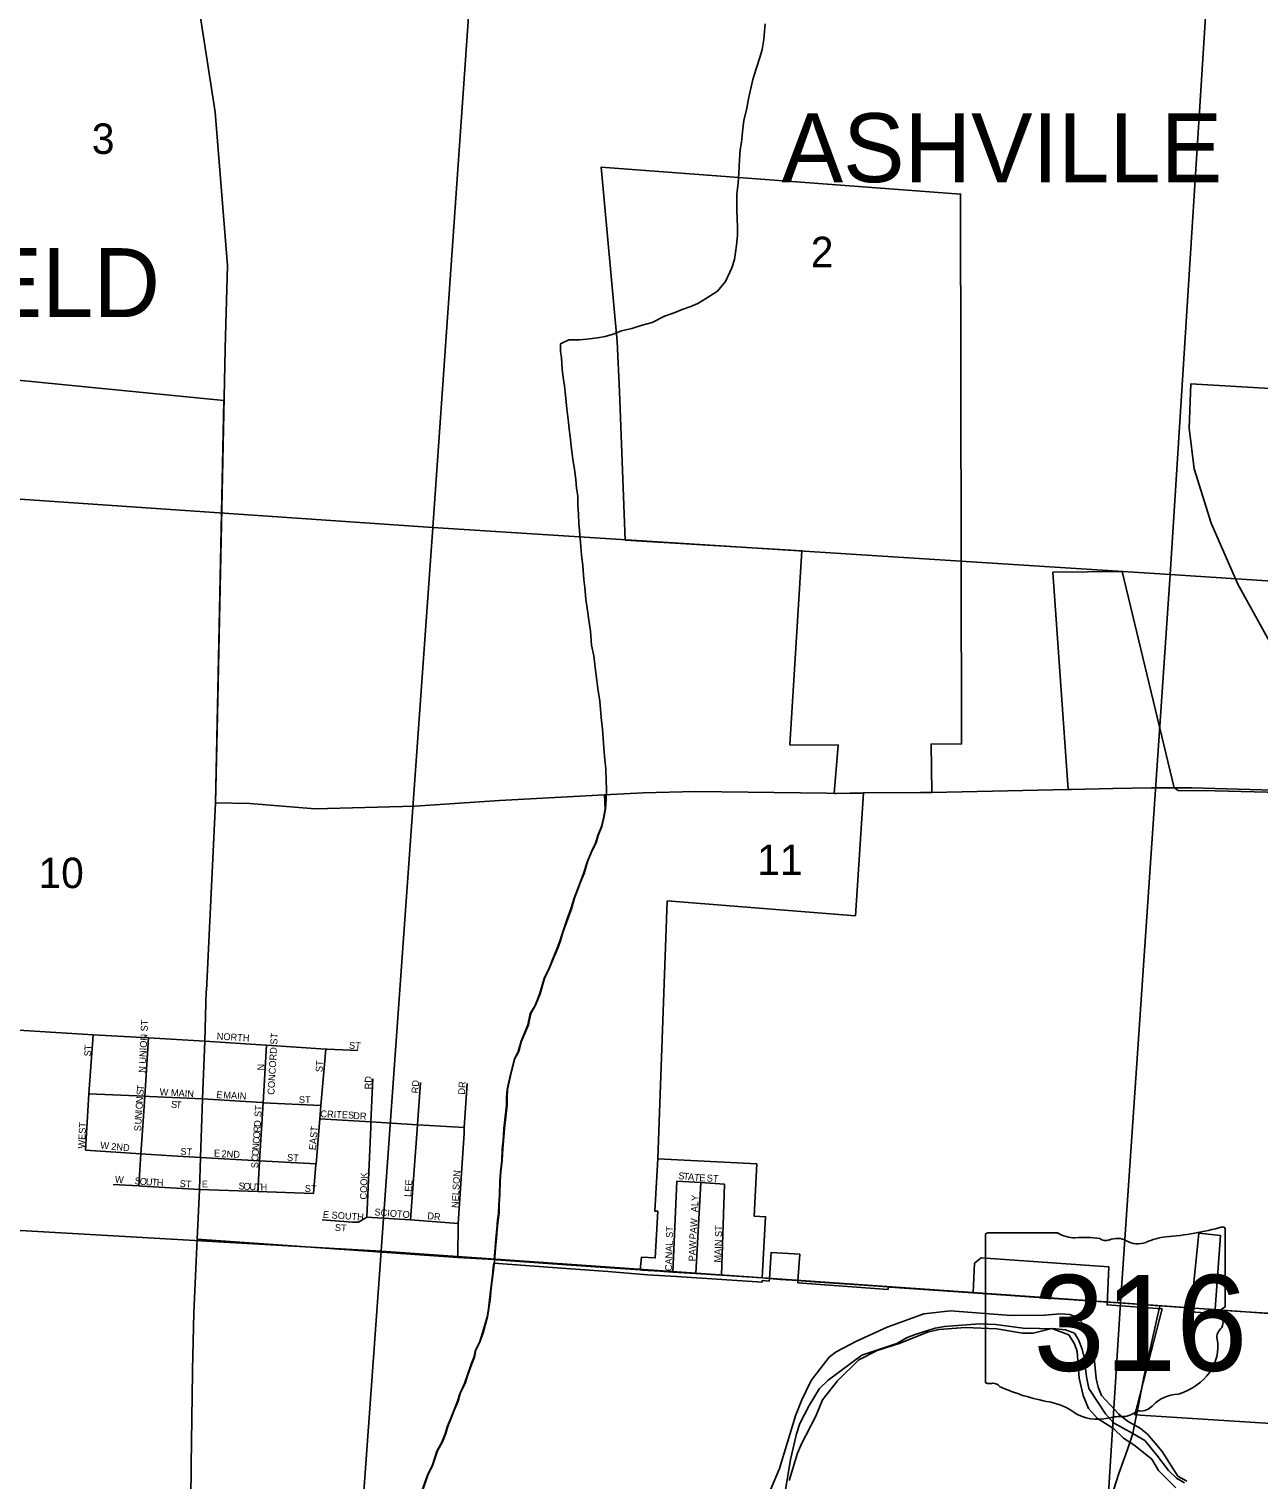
# Model space of a CAD drawing. Extents: x 1643459 to 2064572, y 425441 to 780708.
# Drawn here: x 1830277 to 1839200, y 623125 to 633650 of the extents above; entities that cross this region are included whole.
import ezdxf

# ---------------------------------------------------------------- set-up
doc = ezdxf.new("R2010")
doc.units = 0
for name, color, linetype in [('GM_P_County_Alignment', 7, 'Continuous'), ('GM_X_Adjacent_County', 7, 'Continuous'), ('GM_X_Airport_Class_2', 7, 'Continuous'), ('GM_X_Airport_Class_3', 7, 'Continuous'), ('GM_X_City_Street', 7, 'Continuous'), ('GM_X_Minor_Lake', 7, 'Continuous'), ('GM_X_Rail_Line_Text', 7, 'Continuous'), ('GM_X_State_Route', 7, 'Continuous'), ('GM_X_Unincorporated_Text', 7, 'Continuous'), ('GM_X_US_Route', 7, 'Continuous'), ('PM_P_Cells', 7, 'Continuous'), ('RD_X_Text', 7, 'Continuous'), ('RD_X_Wall', 7, 'Continuous'), ('ST_Details', 7, 'Continuous')]:
    doc.layers.add(name, color=color, linetype=linetype)

msp = doc.modelspace()

# ---------------------------------------------------------------- linework, layer by layer
at = {"layer": 'GM_X_Airport_Class_2'}
for points in [[(1830688, 625512), (1830711, 625921), (1830743, 626350)], [(1831117, 625903), (1831143, 626327)], [(1831552, 626304), (1831996, 626274)], [(1831987, 626065), (1831987, 626065), (1831999, 626274)], [(1831996, 626274), (1831999, 626274), (1832430, 626246), (1832440, 626246)], [(1832359, 625407), (1832359, 625407), (1832360, 625413), (1832387, 625739), (1832395, 625835), (1832430, 626246)], [(1832440, 626246), (1832662, 626235)], [(1831975, 625856), (1831987, 626065)], [(1832756, 625679), (1832756, 625679), (1832758, 625717), (1832772, 626030)], [(1830711, 625921), (1831117, 625903), (1831151, 625902)], [(1833045, 625005), (1833095, 625696), (1833117, 626003)], [(1833433, 625642), (1833435, 625676), (1833456, 625995)], [(1831102, 625686), (1831102, 625686), (1831117, 625903)], [(1831151, 625902), (1831372, 625892), (1831372, 625892)], [(1831372, 625892), (1831537, 625885)], [(1831537, 625885), (1831966, 625857)], [(1831949, 625426), (1831949, 625426), (1831950, 625435), (1831975, 625856)], [(1831966, 625857), (1831975, 625856), (1832395, 625835)], [(1832387, 625739), (1832758, 625717), (1833095, 625696), (1833435, 625676)], [(1831074, 625252), (1831089, 625486), (1831102, 625686)], [(1832727, 625025), (1832756, 625679)], [(1833388, 624733), (1833391, 624979), (1833433, 625635), (1833433, 625642)], [(1830688, 625512), (1831089, 625486), (1831313, 625471)], [(1831313, 625471), (1831313, 625471), (1831521, 625458)], [(1831521, 625458), (1831950, 625435), (1832360, 625413)], [(1831937, 625211), (1831949, 625426)], [(1832342, 625197), (1832359, 625407)], [(1834947, 624627), (1834976, 625287)], [(1834976, 625287), (1835150, 625276), (1835323, 625266)], [(1835114, 624617), (1835150, 625276)], [(1830888, 625263), (1831074, 625252), (1831096, 625251)], [(1831096, 625251), (1831096, 625251), (1831513, 625227)], [(1831513, 625227), (1831937, 625211), (1832342, 625197)], [(1835300, 624604), (1835323, 625266)], [(1832404, 625006), (1832624, 624989), (1832668, 624989), (1832727, 625025)], [(1832727, 625025), (1833045, 625005), (1833391, 624979)]]:
    msp.add_lwpolyline(points, dxfattribs=at)
at = {"layer": 'GM_X_City_Street'}
for points in [[(1838659, 623097), (1838603, 623132), (1838543, 623187), (1838460, 623299), (1838372, 623404), (1838285, 623456), (1838146, 623533), (1838086, 623599), (1838031, 623683), (1837966, 623781), (1837948, 623867), (1837932, 624007), (1837917, 624068), (1837891, 624134), (1837861, 624184), (1837797, 624207), (1837727, 624215), (1837490, 624220), (1837291, 624247), (1837175, 624251), (1836918, 624231), (1836852, 624219), (1836705, 624173), (1836643, 624149), (1836572, 624108), (1836319, 624024), (1836074, 623843), (1836013, 623781), (1835936, 623659), (1835870, 623527), (1835845, 623452), (1835802, 623266), (1835749, 622945)], [(1835749, 622945), (1835802, 623266), (1835845, 623452), (1835870, 623527), (1835936, 623659), (1836013, 623781), (1836074, 623843), (1836319, 624024), (1836572, 624108), (1836643, 624149), (1836705, 624173), (1836852, 624219), (1836918, 624231), (1837175, 624251), (1837291, 624247), (1837490, 624220), (1837727, 624215), (1837797, 624207), (1837861, 624184), (1837891, 624134), (1837917, 624068), (1837932, 624007), (1837948, 623867), (1837966, 623781), (1838031, 623683), (1838086, 623599), (1838146, 623533), (1838285, 623456), (1838372, 623404), (1838460, 623299), (1838543, 623187), (1838603, 623132), (1838659, 623097)]]:
    msp.add_lwpolyline(points, dxfattribs=at)
at = {"layer": 'GM_X_Minor_Lake'}
for points in [[(1838481, 624383), (1838365, 623864), (1838326, 623662)], [(1838326, 623662), (1838295, 623507)], [(1838295, 623507), (1838285, 623456), (1838247, 623339), (1838184, 623166), (1838148, 623052), (1838100, 622903), (1838084, 622769), (1837635, 615362), (1837553, 614083), (1837539, 613880), (1837533, 613820), (1837500, 613782), (1837469, 613757), (1837434, 613737), (1835908, 613841)]]:
    msp.add_lwpolyline(points, dxfattribs=at)
at = {"layer": 'GM_X_Rail_Line_Text'}
for points in [[(1840388, 623458), (1838300, 623591), (1838497, 624360), (1838099, 624388), (1838112, 624664), (1837186, 624730), (1837136, 624691), (1837126, 624478), (1836510, 624519), (1836509, 624501), (1835855, 624548), (1835856, 624565), (1835869, 624756), (1835661, 624769), (1835649, 624580), (1835597, 624584), (1835621, 625028), (1835537, 625033), (1835557, 625412), (1834838, 625450), (1834908, 627321), (1836273, 627213), (1836332, 628105), (1836133, 628101), (1836118, 628101), (1836148, 628452), (1835798, 628453), (1835885, 629861), (1834603, 629940), (1834561, 631019), (1834545, 631381), (1834429, 632648), (1837036, 632451), (1837043, 628461), (1836822, 628459), (1836826, 628109), (1837816, 628130), (1837706, 629707), (1838209, 629711), (1838586, 628143), (1838614, 628123), (1838883, 628120), (1840487, 628080)], [(1823289, 631784), (1831691, 630954), (1831631, 628034), (1831879, 628029), (1832353, 627990), (1833077, 628008), (1833690, 628049), (1834452, 628091), (1834457, 627986), (1834444, 627922), (1834430, 627860), (1834404, 627795), (1834387, 627741), (1834357, 627679), (1834327, 627603), (1834300, 627519), (1834276, 627455), (1834256, 627405), (1834231, 627341), (1834209, 627263), (1834182, 627190), (1834148, 627090), (1834129, 627030), (1834109, 626978), (1834087, 626926), (1834050, 626834), (1834014, 626758), (1833981, 626645), (1833949, 626563), (1833914, 626503), (1833896, 626421), (1833847, 626303), (1833827, 626227), (1833799, 626175), (1833772, 626070), (1833758, 626008), (1833745, 625952), (1833741, 625894), (1833741, 625838), (1833730, 625731), (1833722, 625669), (1833716, 625579), (1833711, 625523), (1833707, 625436), (1833697, 625354), (1833692, 625288), (1833690, 625186), (1833686, 625117), (1833683, 625055), (1833677, 625003), (1833671, 624939), (1833664, 624869), (1833658, 624803), (1833652, 624718), (1834076, 624688), (1834712, 624643), (1834720, 624735), (1834820, 624730), (1834838, 625069), (1834818, 625070), (1834838, 625450), (1835557, 625412), (1835537, 625033), (1835621, 625028), (1835597, 624584), (1835649, 624580), (1835648, 624562), (1835596, 624565), (1835595, 624553), (1834974, 624594), (1834764, 624608), (1834477, 624630), (1834075, 624659), (1833649, 624691), (1833645, 624660), (1833639, 624602), (1833627, 624508), (1833618, 624425), (1833610, 624361), (1833600, 624301), (1833567, 624185), (1833545, 624117), (1833516, 624061), (1833504, 624008), (1833486, 623958), (1833455, 623874), (1833437, 623818), (1833402, 623744), (1833386, 623690), (1833356, 623616), (1833337, 623566), (1833311, 623504), (1833297, 623453), (1833273, 623393), (1833236, 623327), (1833204, 623227), (1833167, 623153), (1833128, 623039)], [(1839797, 628264), (1839046, 629620), (1838853, 630064), (1838731, 630457), (1838695, 630753), (1838707, 631075), (1841089, 630934)]]:
    msp.add_lwpolyline(points, dxfattribs=at)
msp.add_lwpolyline([(1838707, 624338), (1838880, 624327), (1838921, 624893), (1838765, 624909)], close=True, dxfattribs=at)
at = {"layer": 'GM_X_State_Route'}
for points in [[(1828361, 635812), (1833582, 635406), (1833207, 630031), (1828130, 630380)], [(1833582, 635406), (1838893, 635002), (1838557, 629690), (1833207, 630031)], [(1838893, 635002), (1844261, 634633), (1843965, 630056), (1843918, 629340), (1838557, 629690)], [(1828130, 630380), (1833207, 630031), (1832831, 624779), (1827931, 625060)], [(1833207, 630031), (1838557, 629690), (1838196, 624403), (1832831, 624779)], [(1838557, 629690), (1843918, 629340), (1843583, 624695), (1843542, 624018), (1838196, 624403)], [(1832831, 624779), (1832446, 619409), (1827729, 619681), (1827931, 625060)], [(1838196, 624403), (1837858, 619041), (1832446, 619409), (1832831, 624779)], [(1843542, 624018), (1843247, 619225), (1843213, 618737), (1837858, 619041), (1838196, 624403)]]:
    msp.add_lwpolyline(points, close=True, dxfattribs=at)
at = {"layer": 'GM_X_Unincorporated_Text'}
for points in [[(1835656, 623047), (1835723, 623201), (1835839, 623584), (1835884, 623700), (1835951, 623839), (1836082, 624009), (1836134, 624049), (1836281, 624126), (1836504, 624228), (1836768, 624323), (1836962, 624346), (1837402, 624312), (1837644, 624315), (1837761, 624324), (1837829, 624318), (1837881, 624300), (1837943, 624233), (1837981, 624173), (1837995, 624103), (1838020, 623854), (1838033, 623791), (1838059, 623731), (1838183, 623596), (1838247, 623544), (1838339, 623493), (1838395, 623447), (1838497, 623324), (1838612, 623145), (1838676, 623110)], [(1835793, 623113), (1835852, 623313), (1835881, 623381), (1835986, 623580), (1836034, 623700), (1836143, 623838), (1836297, 623990), (1836431, 624057), (1836598, 624111), (1836795, 624192), (1836881, 624210), (1837068, 624225), (1837299, 624214), (1837485, 624183), (1837562, 624183), (1837698, 624218), (1837820, 624172), (1837862, 624107), (1837882, 624051), (1837895, 623858), (1837925, 623730), (1837964, 623637), (1838028, 623565), (1838144, 623492), (1838218, 623421), (1838292, 623373), (1838422, 623268), (1838472, 623187), (1838598, 623060)]]:
    msp.add_lwpolyline(points, dxfattribs=at)
at = {"layer": 'GM_X_US_Route'}
for points in [[(1834296, 629752), (1834286, 629834), (1834280, 629890), (1834275, 629953), (1834267, 630063), (1834263, 630127), (1834260, 630195), (1834258, 630260), (1834250, 630316), (1834244, 630380), (1834235, 630452), (1834223, 630527), (1834213, 630603), (1834202, 630691), (1834196, 630746), (1834190, 630796), (1834180, 630892), (1834169, 630991), (1834163, 631059), (1834153, 631121), (1834146, 631181), (1834140, 631262), (1834132, 631312), (1834132, 631364), (1834193, 631394), (1834271, 631393), (1834325, 631399), (1834401, 631407), (1834456, 631417), (1834516, 631435), (1834576, 631458), (1834651, 631476), (1834725, 631500), (1834797, 631520), (1834888, 631565), (1834958, 631589), (1835016, 631613), (1835079, 631635), (1835129, 631657), (1835193, 631695), (1835272, 631746), (1835330, 631818), (1835377, 631916), (1835395, 631977), (1835403, 632027), (1835410, 632081), (1835416, 632151), (1835416, 632211), (1835413, 632332), (1835413, 632454), (1835422, 632530), (1835426, 632603), (1835431, 632699), (1835437, 632773), (1835445, 632829), (1835456, 632926), (1835464, 632986), (1835484, 633076), (1835495, 633130), (1835511, 633208), (1835529, 633284), (1835552, 633361), (1835578, 633443), (1835595, 633501), (1835609, 633573), (1835613, 633635), (1835618, 633687)], [(1833132, 623040), (1833171, 623154), (1833207, 623228), (1833240, 623329), (1833276, 623395), (1833301, 623455), (1833315, 623505), (1833341, 623567), (1833359, 623617), (1833390, 623691), (1833406, 623745), (1833441, 623819), (1833459, 623875), (1833489, 623960), (1833508, 624010), (1833520, 624062), (1833548, 624118), (1833571, 624186), (1833603, 624302), (1833614, 624362), (1833622, 624427), (1833630, 624509), (1833643, 624603), (1833649, 624661), (1833657, 624732), (1833662, 624804), (1833668, 624870), (1833674, 624940), (1833681, 625004), (1833687, 625057), (1833689, 625119), (1833693, 625187), (1833696, 625289), (1833700, 625355), (1833711, 625438), (1833715, 625524), (1833719, 625580), (1833726, 625670), (1833734, 625733), (1833745, 625839), (1833745, 625895), (1833749, 625953), (1833761, 626009), (1833776, 626072), (1833802, 626176), (1833831, 626228), (1833851, 626304), (1833900, 626422), (1833918, 626504), (1833952, 626565), (1833985, 626647), (1834018, 626759), (1834054, 626835), (1834091, 626927), (1834113, 626979), (1834133, 627031), (1834151, 627091), (1834186, 627192), (1834212, 627264), (1834235, 627342), (1834259, 627406), (1834279, 627456), (1834304, 627520), (1834330, 627604), (1834361, 627681), (1834391, 627743), (1834407, 627797), (1834434, 627861), (1834448, 627923), (1834460, 627987), (1834465, 628055), (1834467, 628132), (1834465, 628192), (1834462, 628280), (1834454, 628346), (1834450, 628401), (1834444, 628467), (1834437, 628567), (1834427, 628652), (1834418, 628770), (1834404, 628862), (1834396, 628921), (1834387, 628997), (1834375, 629099), (1834359, 629178), (1834350, 629280), (1834338, 629360), (1834328, 629429), (1834317, 629511), (1834309, 629597), (1834303, 629653), (1834296, 629752)]]:
    msp.add_lwpolyline(points, dxfattribs=at)
at = {"layer": 'RD_X_Text'}
for points in [[(1836744, 628108), (1836826, 628109), (1837816, 628130), (1837840, 628130)], [(1837840, 628130), (1838139, 628136), (1838421, 628142), (1838459, 628143), (1838466, 628143)], [(1838466, 628143), (1838623, 628143)], [(1838623, 628143), (1838713, 628143), (1839816, 628110), (1839876, 628107)], [(1831631, 628034), (1831879, 628029), (1832353, 627990), (1833077, 628008), (1833690, 628049), (1834452, 628091), (1834499, 628093)], [(1834499, 628093), (1834732, 628105), (1835112, 628115), (1836065, 628102)], [(1836065, 628102), (1836118, 628101), (1836133, 628101), (1836326, 628104)], [(1836326, 628104), (1836332, 628105), (1836744, 628108)], [(1830186, 626383), (1830240, 626380), (1830743, 626350), (1831143, 626327), (1831552, 626304)], [(1831497, 624865), (1833388, 624733), (1833652, 624718), (1833666, 624717)], [(1833666, 624717), (1834384, 624666), (1834712, 624643), (1834724, 624642)], [(1834724, 624642), (1834767, 624639), (1834856, 624633), (1834883, 624631)], [(1834883, 624631), (1834947, 624627), (1835114, 624617), (1835300, 624604), (1835597, 624584), (1835649, 624580), (1835677, 624578)], [(1835677, 624578), (1835730, 624574)], [(1835730, 624574), (1835856, 624565), (1835941, 624559)], [(1835941, 624559), (1836510, 624519), (1836523, 624518)], [(1836523, 624518), (1837158, 624473)], [(1837158, 624473), (1837533, 624447), (1838216, 624401)], [(1838216, 624401), (1838481, 624383)], [(1838481, 624383), (1838840, 624357)], [(1838840, 624357), (1838994, 624346)], [(1838994, 624346), (1839063, 624341), (1839302, 624326)]]:
    msp.add_lwpolyline(points, dxfattribs=at)
at = {"layer": 'RD_X_Wall'}
for points in [[(1831701, 631333), (1831718, 631932), (1831628, 633047), (1830807, 638339), (1830530, 640486), (1831027, 646299)], [(1831642, 628558), (1831701, 631324), (1831701, 631333)], [(1831631, 628034), (1831642, 628558)], [(1831564, 626671), (1831631, 628034)], [(1831552, 626304), (1831563, 626668), (1831564, 626671)], [(1831513, 625225), (1831513, 625227), (1831521, 625458), (1831537, 625885), (1831552, 626304)], [(1831488, 624654), (1831497, 624865), (1831513, 625225)], [(1831464, 623914), (1831474, 624331), (1831488, 624654)], [(1831454, 623227), (1831463, 623898), (1831464, 623914)], [(1831437, 621883), (1831441, 622392), (1831450, 622963), (1831454, 623227)]]:
    msp.add_lwpolyline(points, dxfattribs=at)
at = {"layer": 'ST_Details'}
for p, q in [((1837216, 624892), (1837216, 623836)), ((1837743, 624911), (1837233, 624911)), ((1838956, 624384), (1838956, 624937)), ((1838956, 624384), (1838956, 624384))]:
    msp.add_line(p, q, dxfattribs=at)
for centre, major_axis, start_param, end_param in [((1837236, 624895), (20.2, 0), 1.712693, 3.28349), ((1837864, 625033), (196, 0), 4.042523, 4.731795), ((1837929, 624317), (702, 0), 1.404758, 1.657858), ((1838088, 624900), (56.4, 0), 3.836095, 5.185415), ((1838171, 624778), (117, 0), 0.950623, 2.079405), ((1838322, 624945), (141, 0), 4.081561, 5.145723), ((1838572, 624588), (371, 0), 1.699011, 2.107814), ((1838336, 626351), (1845, 0), 4.814394, 5.042369), ((1838937, 624939), (19.4, 0), 6.141152, 7.989035), ((1838952, 624343), (30, 0), 1.883978, 3.671073), ((1838761, 624274), (180, 0), 5.934695, 6.695948), ((1838935, 624382), (20.7, 0), 5.05454, 6.418171), ((1839026, 624153), (131, 0), 2.387724, 3.262537), ((1838440, 624082), (462, 0), 5.101752, 6.440018), ((1837236, 623833), (20.3, 0), 3.00124, 4.508301), ((1837239, 623942), (155, 0), 4.665946, 4.897461), ((1837271, 623775), (56, 0), 0.519207, 1.627899), ((1837977, 624724), (1333, 0), 4.195997, 4.488961), ((1838634, 623539), (253, 0), 1.647645, 2.488434), ((1837580, 623361), (417, 0), 0.823519, 1.323587), ((1838031, 623770), (265, 0), 4.026481, 4.996735), ((1838203, 623690), (141, 0), 4.691044, 5.507374), ((1838331, 623588), (39.7, 0), 1.147584, 2.315152), ((1838314, 623733), (149, 0), 4.937069, 5.64225), ((1838184, 623404), (217, 0), 1.495662, 1.94098)]:
    msp.add_ellipse(centre, major_axis=major_axis, ratio=0.8, start_param=start_param, end_param=end_param, dxfattribs=at)

# ---------------------------------------------------------------- texts
at = {"layer": 'GM_P_County_Alignment'}
for s, p in [('ASHVILLE', (1835737, 632538)), ('SOUTH BLOOMFIELD', (1824392, 631559))]:
    msp.add_text(s, height=500, rotation=0, dxfattribs=at).set_placement(p)
at = {"layer": 'GM_X_Adjacent_County'}
for s, p in [('3', (1830733, 632743)), ('2', (1835949, 631921)), ('11', (1835560, 627509)), ('10', (1830346, 627414))]:
    msp.add_text(s, height=221, rotation=0, dxfattribs=at).set_placement(p)
at = {"layer": 'GM_X_Airport_Class_3'}
for s, rotation, p in [('N UNION ST', 87.0659, (1831122, 626072)), ('NORTH', 356.4211, (1831638, 626315)), ('CONCORD ST', 86.7505, (1832057, 625913)), ('ST', 86.4254, (1830726, 626191)), ('ST', 356.1734, (1832597, 626249)), ('N', 90, (1831984, 626090)), ('ST', 86.4262, (1832406, 626077)), ('RD', 90, (1832763, 625953)), ('RD', 86.8222, (1833102, 625923)), ('S', 85.8171, (1831107, 625908)), ('T', 85.7878, (1831110, 625943)), ('W MAIN', 356.8193, (1831224, 625910)), ('E', 352.8783, (1831634, 625892)), ('MAIN', 356.9016, (1831686, 625888)), ('DR', 86.8222, (1833440, 625914)), ('O', 85.7773, (1831100, 625807)), ('N', 85.804, (1831103, 625851)), ('S', 355.9533, (1831306, 625820)), ('T', 356.9242, (1831342, 625817)), ('ST', 86.4118, (1831962, 625751)), ('ST', 0, (1832235, 625853)), ('CRITES', 357.6154, (1832390, 625751)), ('WEST', 86.9833, (1830682, 625522)), ('U', 86.2164, (1831092, 625697)), ('N', 85.7991, (1831095, 625741)), ('I', 85.7991, (1831098, 625785)), ('D', 85.7365, (1831958, 625679)), ('DR', 356.989, (1832628, 625738)), ('S', 89.153, (1831091, 625649)), ('C', 85.7476, (1831949, 625556)), ('O', 85.7337, (1831952, 625595)), ('R', 85.7223, (1831955, 625639)), ('EAST', 85.0974, (1832358, 625510)), ('W', 355.6039, (1830793, 625523)), ('2ND', 355.7579, (1830872, 625514)), ('ST', 356.4254, (1831374, 625479)), ('E', 0, (1831619, 625465)), ('2ND', 357.8798, (1831673, 625461)), ('O', 85.7555, (1831943, 625468)), ('N', 85.7337, (1831946, 625512)), ('S', 90, (1831940, 625381)), ('C', 86.257, (1831940, 625429)), ('ST', 356.4254, (1832148, 625435)), ('W', 355.6039, (1830899, 625276)), ('S', 351.4719, (1831040, 625267)), ('O', 354.5414, (1831078, 625262)), ('U', 357.2682, (1831124, 625257)), ('T', 357.3527, (1831168, 625255)), ('H', 357.3329, (1831203, 625254)), ('ST', 356.4254, (1831369, 625245)), ('E', 0, (1831531, 625241)), ('S', 356.4731, (1831796, 625228)), ('O', 356.4564, (1831831, 625226)), ('COOK', 88.5265, (1832728, 625153)), ('LEE', 85.4282, (1833049, 625171)), ('NELSON', 86.8756, (1833392, 625091)), ('S', 353.9796, (1834986, 625303)), ('T', 354.0062, (1835022, 625299)), ('A', 353.9784, (1835057, 625295)), ('T', 353.9796, (1835100, 625291)), ('E', 357.4023, (1835139, 625287)), ('ST', 356.4254, (1835193, 625285)), ('U', 356.4573, (1831875, 625223)), ('T', 358.3479, (1831921, 625220)), ('H', 359.9028, (1831957, 625219)), ('ST', 356.1734, (1832276, 625210)), ('ALY', 88.0261, (1835130, 625060)), ('E SOUTH', 356.0569, (1832408, 625021)), ('SCIOTO', 355.4242, (1832782, 625039)), ('ST', 356.4254, (1832495, 624926)), ('DR', 353.9946, (1833165, 625012)), ('CANAL ST', 88.3163, (1834941, 624633)), ('PAW', 85.817, (1835117, 624863)), ('MAIN ST', 87.9915, (1835297, 624695)), ('PAW', 88.1465, (1835112, 624704))]:
    msp.add_text(s, height=50, rotation=rotation, dxfattribs=at).set_placement(p)
at = {"layer": 'PM_P_Cells'}
for s in ['s', 'r']:
    msp.add_text(s, height=1, dxfattribs=at).set_placement((1838066, 624294))
msp.add_text('316', height=1, rotation=0, dxfattribs=at).set_placement((1837713, 624221))
at = {"layer": 'ST_Details'}
msp.add_text('316', height=696.1, dxfattribs=at).set_placement((1837564, 623910))

doc.saveas('drawing.dxf')
